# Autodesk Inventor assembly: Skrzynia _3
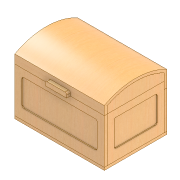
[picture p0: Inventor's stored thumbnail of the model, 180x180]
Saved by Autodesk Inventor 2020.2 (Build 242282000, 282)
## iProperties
Manager: www.cadconsulting.pl
Company: Fabian Stasiak CAD Consulting
Created: 2019-06
Part Number: Skrzynia _3
Document SubType Name: Assembly
Designer: F.Stasiak
Author: F.Stasiak
Subject: Zbiór ćwiczeń. Autodesk Inventor 2020. Kurs podstawowy
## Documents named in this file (7)
- C:\2020_Kurs_podstawowy\R6 Zespoły\Wiązania\Skrzynia I\Skrzynia _3.iam
- C:\2020_Kurs_podstawowy\R6 Zespoły\Wiązania\Skrzynia I\Wieko_2.iam
- C:\2020_Kurs_podstawowy\R6 Zespoły\Wiązania\Skrzynia I\Pudło_1.iam
- C:\2020_Kurs_podstawowy\R6 Zespoły\Wiązania\Skrzynia I\Zawias1.ipt
- C:\2020_Kurs_podstawowy\R6 Zespoły\Wiązania\Skrzynia I\Zawias2.ipt
- C:\2020_Kurs_podstawowy\R6 Zespoły\Wiązania\Skrzynia I\Zawias1_LEWY_1.ipt
- C:\2020_Kurs_podstawowy\R6 Zespoły\Wiązania\Skrzynia I\Zawias2_LEWY_1.ipt
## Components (6 placed, 6 different names)
1. Pudło_1:1 [sub-assembly]
2. Wieko_2:1 [sub-assembly]
3. Zawias1:1 — Wstawiające:1
4. Zawias2:1 — Wstawiające:1
5. Zawias1_LEWY_1:1 — Wstawiające:2
6. Zawias2_LEWY_1:1 — Wstawiające:2
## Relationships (2: Insert 2)
- Wstawiające:1 [Insert]: Zawias1:1 ↔ Zawias2:1
- Wstawiające:2 [Insert]: Zawias1_LEWY_1:1 ↔ Zawias2_LEWY_1:1
